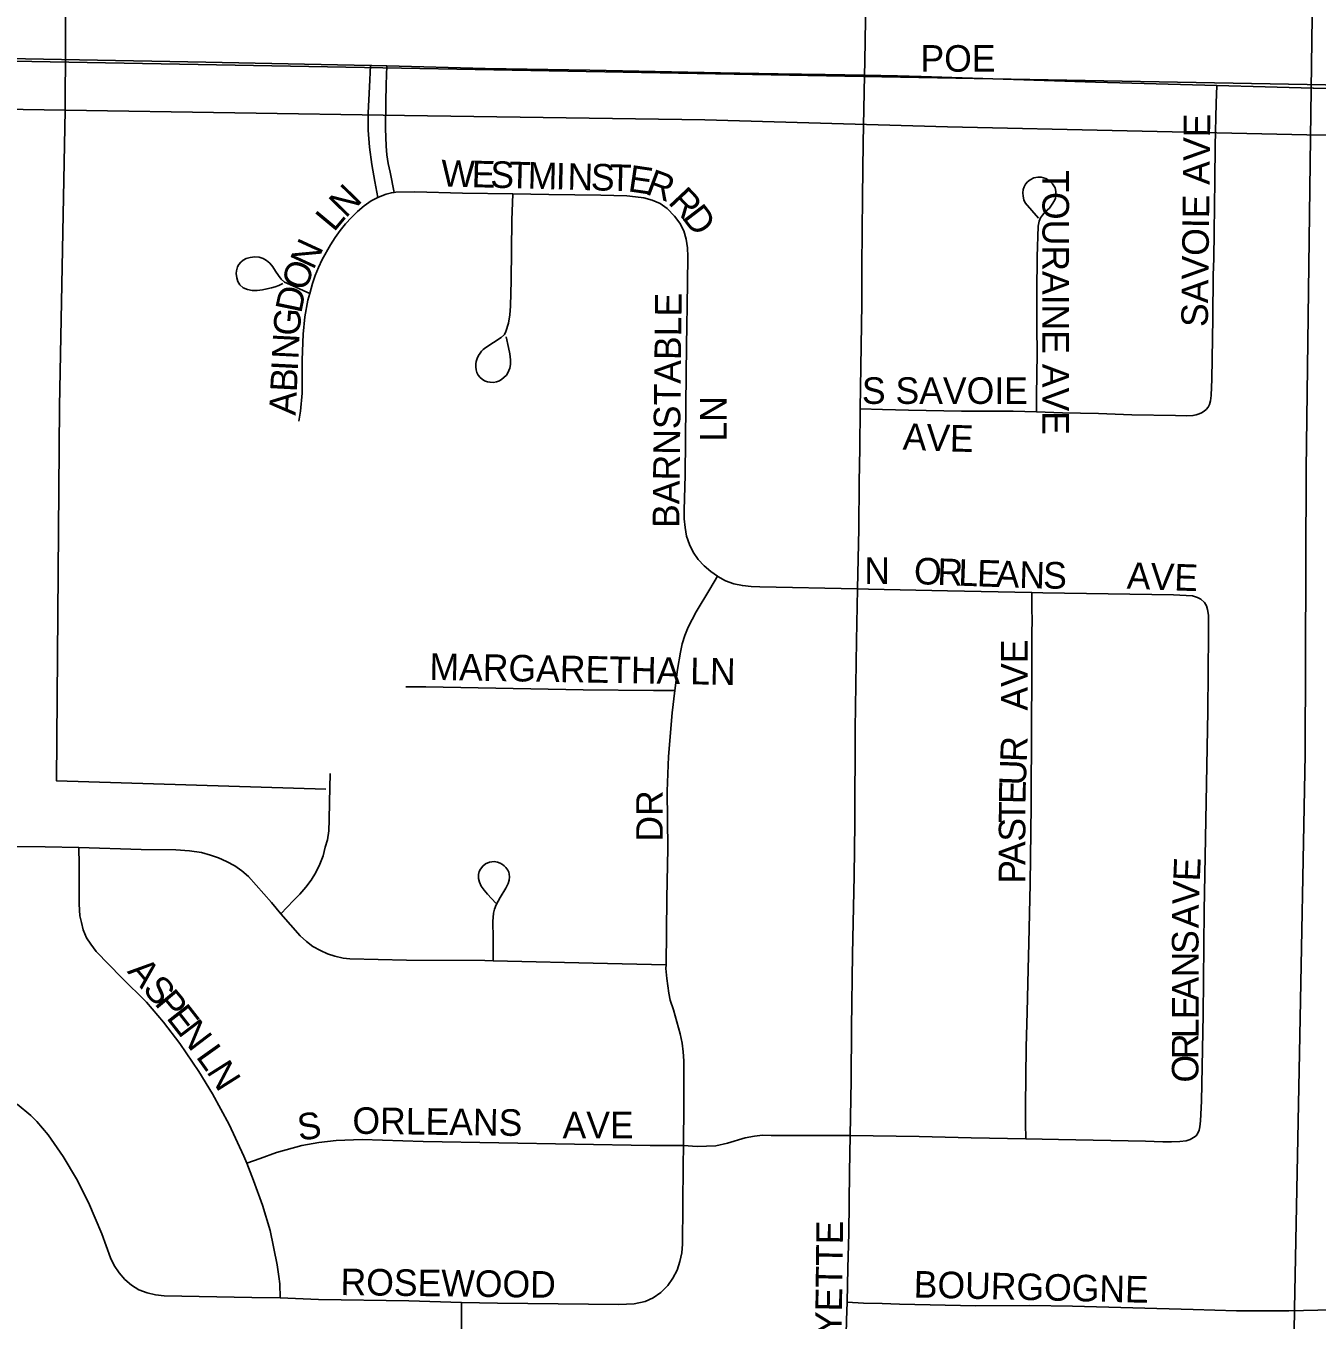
# Model space of a CAD drawing. Extents: x 1443599 to 1910620, y 1028088 to 1361369.
# Drawn here: x 1643273 to 1645702, y 1233402 to 1235837 of the extents above; entities that cross this region are included whole.
import ezdxf

# ---------------------------------------------------------------- set-up
doc = ezdxf.new("R2010")
doc.units = 0
for name, color, linetype in [('GM_X_City_Street', 7, 'Continuous'), ('GM_X_City_Street_Text', 7, 'Continuous'), ('GM_X_Minor_River', 7, 'Continuous'), ('GM_X_Section', 7, 'Continuous')]:
    doc.layers.add(name, color=color, linetype=linetype)

msp = doc.modelspace()

# ---------------------------------------------------------------- linework, layer by layer
at = {"layer": 'GM_X_City_Street'}
for points in [[(1644850.4, 1235743.8), (1644850.8, 1235769.3), (1644852.8, 1235887.3), (1644854.7, 1235951.3)], [(1642046.8, 1235796.5), (1642151.4, 1235793.8), (1642266.3, 1235792), (1642512.4, 1235789), (1642758.5, 1235783.8), (1643135.9, 1235776.9), (1643611.7, 1235768.1), (1643921, 1235761.9)], [(1643934.9, 1235514), (1643929.4, 1235543.9), (1643923.5, 1235575.9), (1643919.3, 1235608.2), (1643917, 1235640.6), (1643916.9, 1235673.2), (1643919.2, 1235721.9), (1643921, 1235761.9)], [(1643921, 1235761.9), (1643923.5, 1235761.8), (1643952, 1235761.1)], [(1643965.8, 1235523.4), (1643958.1, 1235561.2), (1643954.7, 1235577.5), (1643952.3, 1235593.9), (1643950.7, 1235610.4), (1643949.4, 1235643.5), (1643949.9, 1235693.3), (1643950.9, 1235726.4), (1643952, 1235761.1)], [(1643952, 1235761.1), (1644136.7, 1235756.3), (1644333.7, 1235753), (1644579.7, 1235748.2), (1644687.8, 1235746.6), (1644776.7, 1235745.3), (1644850.4, 1235743.8)], [(1644842.4, 1235116.3), (1644845.2, 1235313.9), (1644845.6, 1235384.5), (1644846.8, 1235514.9), (1644847.9, 1235616.7), (1644850.4, 1235743.8)], [(1644850.4, 1235743.8), (1644912.8, 1235742.4), (1644957.1, 1235741.5), (1645285.1, 1235730.7), (1645513, 1235724.4)], [(1645489.1, 1235111.6), (1645492.9, 1235114.7), (1645496.7, 1235119.5), (1645499.6, 1235124.5), (1645501.5, 1235131.5), (1645502.7, 1235141.3), (1645503.8, 1235171.8), (1645505.7, 1235286.7), (1645506.4, 1235367.4), (1645507.4, 1235399.3), (1645508, 1235448.4), (1645509.4, 1235546.1), (1645510.3, 1235611.2), (1645512.2, 1235691.4), (1645513, 1235724.4)], [(1645513, 1235724.4), (1645604.1, 1235721.9), (1645694.6, 1235719.5), (1645695.2, 1235719.4), (1645793.6, 1235717.1), (1645892, 1235714.9)], [(1645173.7, 1235110.4), (1645174, 1235141.3), (1645175, 1235220.5), (1645174.5, 1235270.1), (1645174.4, 1235336.4), (1645175.3, 1235402.2), (1645177, 1235459.9), (1645179.2, 1235469.2), (1645181.7, 1235475.7), (1645185.5, 1235480.7), (1645191.2, 1235487.1), (1645198.2, 1235493.7), (1645203.7, 1235501.1), (1645207.8, 1235508), (1645209.5, 1235512.2), (1645210.6, 1235517.4), (1645210.4, 1235525), (1645208.8, 1235531.9), (1645204.3, 1235539.5), (1645198.2, 1235545.3), (1645191.3, 1235549.5), (1645182.6, 1235551.8), (1645176.3, 1235551.8), (1645169, 1235550.6), (1645161.8, 1235547.1), (1645156.8, 1235542.9), (1645153.5, 1235538.6), (1645150.5, 1235533.6), (1645149.2, 1235528.6), (1645148.5, 1235522.5), (1645149, 1235516), (1645150.3, 1235509.5), (1645152.7, 1235503.9), (1645177.6, 1235475.1)], [(1643806.9, 1235332.9), (1643811.9, 1235352), (1643817.1, 1235367.3), (1643823.2, 1235382.2), (1643830.2, 1235396.8), (1643846.1, 1235425), (1643854.8, 1235438.6), (1643864.3, 1235451.7), (1643874.5, 1235464.2), (1643885.5, 1235476), (1643897, 1235487.5), (1643909.2, 1235498), (1643922.4, 1235507.3), (1643934.9, 1235514)], [(1643934.9, 1235514), (1643936.1, 1235514.6), (1643950.8, 1235520.2)], [(1643950.8, 1235520.2), (1643960.5, 1235522.6), (1643965.8, 1235523.4)], [(1643965.8, 1235523.4), (1643968.9, 1235523.8), (1644004.6, 1235524.1), (1644094.3, 1235521.6), (1644189.1, 1235520.5)], [(1644176.7, 1235251.9), (1644180.9, 1235231.7), (1644183.5, 1235219.7), (1644184.4, 1235208.4), (1644184.4, 1235199.4), (1644183.2, 1235192.9), (1644181.5, 1235188), (1644179.9, 1235184.1), (1644176.9, 1235179.8), (1644172.1, 1235175), (1644168.4, 1235172.2), (1644163.9, 1235169), (1644158.5, 1235167), (1644152.4, 1235165.8), (1644146.3, 1235166.1), (1644141.2, 1235167), (1644135.8, 1235168.8), (1644131.3, 1235171.7), (1644127.5, 1235175.3), (1644123.8, 1235179.4), (1644121.4, 1235184.5), (1644120.3, 1235189.4), (1644119.1, 1235195.3), (1644119.3, 1235200.7), (1644120, 1235205.5), (1644121.8, 1235210.8), (1644124.5, 1235216.5), (1644127.4, 1235221), (1644130.3, 1235224.4), (1644133.5, 1235228), (1644138.4, 1235231.8), (1644167.2, 1235250.1), (1644173.3, 1235256.1), (1644176, 1235261.9), (1644180.8, 1235277.3), (1644183.5, 1235293.2), (1644184.6, 1235309.3), (1644186, 1235357.8), (1644187.2, 1235470.9), (1644189.1, 1235520.5)], [(1644189.1, 1235520.5), (1644256.8, 1235519.6), (1644354.6, 1235518.3), (1644403.4, 1235516.7), (1644419.6, 1235515.2), (1644435.6, 1235512.8), (1644451.1, 1235508.8), (1644465.9, 1235502.3), (1644479.2, 1235492.9), (1644493.2, 1235478.6)], [(1644574, 1234801.3), (1644561.3, 1234810.1), (1644548.7, 1234820.7), (1644537.6, 1234832.8), (1644528.2, 1234846.3), (1644521, 1234861), (1644515.9, 1234876.6), (1644512.9, 1234892.8), (1644511.5, 1234909.2), (1644511.3, 1234925.6), (1644513, 1234991.4), (1644514.5, 1235123), (1644515.9, 1235236.8), (1644516.4, 1235271.2), (1644516.9, 1235311.2), (1644517.4, 1235353.1), (1644517.9, 1235402.5), (1644517.3, 1235419.1), (1644515.2, 1235435.4), (1644510.8, 1235451), (1644503.1, 1235465.5), (1644493.2, 1235478.6)], [(1643756.3, 1235351.9), (1643748.9, 1235348.1), (1643742, 1235345.5), (1643734.9, 1235343.5), (1643726.5, 1235341.7), (1643718, 1235340.1), (1643708.1, 1235338.6), (1643698.9, 1235338.8), (1643689.7, 1235340.4), (1643681.6, 1235343.9), (1643675.5, 1235349.3), (1643671.6, 1235355.7), (1643669.6, 1235362.8), (1643668.8, 1235370.5), (1643669.1, 1235376.1), (1643670.9, 1235383), (1643673.6, 1235387.6), (1643677.7, 1235392.4), (1643681.6, 1235396), (1643687.4, 1235399), (1643695, 1235401.1), (1643703.5, 1235402.4), (1643711.8, 1235401.3), (1643719.5, 1235399.3), (1643725.4, 1235395.5), (1643732, 1235389.9), (1643737.4, 1235383), (1643742.8, 1235375.1), (1643748, 1235366.8), (1643753.2, 1235359.8), (1643759.5, 1235354.4), (1643774.9, 1235347.4), (1643806.9, 1235332.9)], [(1643786.4, 1235093.2), (1643789.7, 1235111.7), (1643793, 1235145.8), (1643792.7, 1235176), (1643792.7, 1235208.4), (1643794.5, 1235256.8), (1643797.8, 1235289), (1643803.7, 1235320.8), (1643806.9, 1235332.9)], [(1644837.4, 1234777.6), (1644839.8, 1234890.7), (1644840.3, 1234978.5), (1644841.4, 1235042.1), (1644842.4, 1235116.3)], [(1644842.4, 1235116.3), (1644884.6, 1235115.2), (1644933, 1235114), (1645033.1, 1235111.6), (1645129.9, 1235111.7), (1645173.7, 1235110.4)], [(1645173.7, 1235110.4), (1645222.8, 1235108.9), (1645290.3, 1235107.2), (1645353.3, 1235105.2), (1645435.5, 1235103.8), (1645456.7, 1235102.9), (1645468.1, 1235103.6), (1645474.4, 1235104.8), (1645480.1, 1235106.5), (1645484.4, 1235108.4), (1645489.1, 1235111.6)], [(1644493.7, 1234586.2), (1644498.5, 1234625.9), (1644504.1, 1234658.3), (1644507.8, 1234674.3), (1644512.5, 1234690), (1644518.5, 1234705.3), (1644534, 1234734.3), (1644559.3, 1234776.7), (1644574, 1234801.3)], [(1644837.4, 1234777.6), (1644653.5, 1234781.5), (1644637, 1234782.1), (1644620.7, 1234783.7), (1644604.6, 1234787.1), (1644589.3, 1234792.9), (1644574.9, 1234800.7), (1644574, 1234801.3)], [(1644823.7, 1233749.2), (1644825.6, 1233852.8), (1644826.1, 1233952.4), (1644827.7, 1234090.1), (1644830.8, 1234237.6), (1644832.2, 1234336.8), (1644833.2, 1234514.1), (1644835.4, 1234680.1), (1644837.4, 1234777.6)], [(1644837.4, 1234777.6), (1644858, 1234777.2), (1645006.6, 1234774), (1645165, 1234770.8)], [(1645153.7, 1233742.9), (1645153.4, 1233771.6), (1645153.1, 1233804.5), (1645154.7, 1233915.6), (1645156.7, 1233981.3), (1645158.6, 1234062), (1645159.5, 1234111.1), (1645162, 1234222.9), (1645163.9, 1234370.3), (1645164.1, 1234386.7), (1645164.9, 1234625.9), (1645165.1, 1234641.6), (1645165.3, 1234657.7), (1645165.5, 1234690.4), (1645165.7, 1234722.3), (1645165.5, 1234736.2), (1645165, 1234770.8)], [(1645165, 1234770.8), (1645185.6, 1234770.3), (1645431.4, 1234766.1), (1645467.1, 1234764.4), (1645476.5, 1234761.6), (1645483.2, 1234758.3)], [(1645474.2, 1233748.7), (1645477.6, 1233754), (1645480, 1233759.2), (1645481.2, 1233765.7), (1645482.7, 1233776.6), (1645484.4, 1233813.6), (1645487.6, 1233976.4), (1645489.6, 1234171.8), (1645496.5, 1234547.4), (1645497.5, 1234693), (1645497.3, 1234728), (1645495.9, 1234738.9), (1645494, 1234745.5), (1645489.8, 1234752.1), (1645483.2, 1234758.3)], [(1643987.5, 1234593.5), (1644025.4, 1234593.2), (1644321.6, 1234587.7), (1644453.3, 1234586.6), (1644493.7, 1234586.2)], [(1644477.1, 1234070.6), (1644478.6, 1234195.4), (1644480.6, 1234290), (1644479.1, 1234396.8), (1644481.8, 1234462), (1644488.6, 1234544.3), (1644493.7, 1234586.2)], [(1643752.6, 1234166.2), (1643776.7, 1234191.2), (1643788.4, 1234203.3), (1643799.4, 1234216.2), (1643809.4, 1234229.9), (1643818.3, 1234244.3), (1643825.8, 1234259.4), (1643832, 1234275.2), (1643836.3, 1234291.4), (1643840.5, 1234305.5), (1643842.8, 1234322.5), (1643843.4, 1234342.8), (1643843.9, 1234376.6), (1643845.6, 1234430.2)], [(1643072.3, 1234178.3), (1643073.4, 1234194.9), (1643075, 1234209.3), (1643078.3, 1234224.2), (1643080.8, 1234231.1), (1643084.1, 1234238.7), (1643088.4, 1234245.9), (1643092.7, 1234252.4), (1643098.5, 1234259.3), (1643104.3, 1234265.3), (1643110.4, 1234270.1), (1643115.3, 1234274), (1643121.9, 1234278.3), (1643128.6, 1234282.3), (1643137, 1234286.3), (1643144.4, 1234289.2), (1643153, 1234291.1), (1643161.8, 1234291.9), (1643194.4, 1234293.5), (1643309.4, 1234292.1), (1643372.8, 1234290.9)], [(1643688.4, 1233697.3), (1643683.3, 1233710.4), (1643655.2, 1233769.8), (1643624.2, 1233827.5), (1643598.7, 1233869.5), (1643562.4, 1233922.2), (1643532, 1233962.7), (1643500.1, 1234000.1), (1643452.7, 1234046.4), (1643405.1, 1234095.4), (1643395, 1234109), (1643387.2, 1234121.4), (1643381, 1234136.2), (1643377.5, 1234149.9), (1643374.7, 1234162.7), (1643373.2, 1234184.5), (1643373.5, 1234258.8), (1643372.8, 1234290.9)], [(1643372.8, 1234290.9), (1643489.8, 1234287.5), (1643555, 1234286.4), (1643581, 1234284.7), (1643603.1, 1234281.4), (1643620.1, 1234276.7), (1643635.6, 1234271.4), (1643650.6, 1234264.6), (1643665.8, 1234256.5), (1643679.5, 1234246.9), (1643692.1, 1234236.3), (1643735.2, 1234187.4), (1643752.6, 1234166.2)], [(1644152.3, 1234078.1), (1644151.7, 1234120.2), (1644151.3, 1234151.8), (1644152.7, 1234167.7), (1644154.3, 1234175.1), (1644157.5, 1234183.1), (1644165.1, 1234197), (1644175.6, 1234214.5), (1644180.3, 1234223.5), (1644182.1, 1234229.9), (1644182.6, 1234236.1), (1644182.4, 1234240.7), (1644181.5, 1234244.8), (1644179.8, 1234248.5), (1644176, 1234253.5), (1644172.7, 1234256.7), (1644169.4, 1234259.2), (1644165.4, 1234261.7), (1644160, 1234263.5), (1644153.7, 1234264.5), (1644145.1, 1234263.6), (1644137.8, 1234260.4), (1644132.3, 1234256), (1644128.1, 1234250.3), (1644125.9, 1234245.6), (1644124.5, 1234240.1), (1644124.3, 1234232.6), (1644126.1, 1234226), (1644129.4, 1234218.4), (1644134.8, 1234210.5), (1644141.5, 1234203.4), (1644157.3, 1234186.1)], [(1643752.6, 1234166.2), (1643788.9, 1234124.7), (1643800.6, 1234114.2), (1643812.6, 1234104.8), (1643827.4, 1234097.2), (1643840.3, 1234091.3), (1643854, 1234086.7), (1643869.9, 1234083.1), (1643882.2, 1234081.7), (1643989.1, 1234079.3), (1644136.2, 1234078.4), (1644152.3, 1234078.1)], [(1644152.3, 1234078.1), (1644367, 1234072.7), (1644477.1, 1234070.6)], [(1644509.8, 1233730.3), (1644510.9, 1233807.8), (1644510.6, 1233889.8), (1644509.5, 1233906.5), (1644507.3, 1233923.1), (1644504, 1233940.4), (1644491, 1233985.4), (1644485.1, 1234004.1), (1644482.4, 1234016.9), (1644478.9, 1234044.5), (1644477, 1234063.6), (1644477.1, 1234070.6)], [(1643256.9, 1233808.4), (1643282.1, 1233787.2), (1643293.8, 1233775.6), (1643315, 1233750.5), (1643343.3, 1233710.1), (1643368.6, 1233667.6), (1643390.8, 1233623.5), (1643415.9, 1233564.3), (1643432, 1233519.3), (1643439.1, 1233504.5), (1643448.3, 1233490.9), (1643459.2, 1233478.5), (1643471.7, 1233467.8), (1643485.7, 1233459.3), (1643501, 1233453.1), (1643517, 1233449.5), (1643533.4, 1233447.9), (1643697.9, 1233444.8), (1643751.4, 1233443.8)], [(1643688.4, 1233697.3), (1643713.7, 1233706.3), (1643744.6, 1233717.2), (1643792.1, 1233730.2), (1643824.2, 1233736.4), (1643856.8, 1233739.9), (1643905.9, 1233741.5), (1644020.2, 1233738.2), (1644447.1, 1233730.2), (1644509.8, 1233730.3)], [(1644509.8, 1233730.3), (1644535.5, 1233728.6), (1644570.6, 1233730), (1644593, 1233735), (1644625.8, 1233745), (1644643.6, 1233748.3), (1644658.3, 1233749.7), (1644674.7, 1233749.5), (1644805.8, 1233749.5), (1644823.7, 1233749.2)], [(1644817.6, 1233435.6), (1644819.4, 1233500), (1644820.7, 1233565.6), (1644822.5, 1233680.3), (1644823.7, 1233749.2)], [(1644823.7, 1233749.2), (1644953.2, 1233747.4), (1645051.4, 1233744.9), (1645153.7, 1233742.9)], [(1645153.7, 1233742.9), (1645215.3, 1233741.7), (1645379.1, 1233738.4), (1645411.5, 1233737.7), (1645427.6, 1233737.7), (1645443.7, 1233738.3), (1645455.2, 1233739.3), (1645463, 1233741.6), (1645469.1, 1233745.3), (1645474.2, 1233748.7)], [(1644092.4, 1233435.3), (1644160.4, 1233434.2), (1644388.6, 1233431.1), (1644417.2, 1233432.7), (1644438.2, 1233437.1), (1644452.8, 1233444.1), (1644467.3, 1233453.8), (1644480.8, 1233467.3), (1644490, 1233480.8), (1644498.1, 1233495.9), (1644503.1, 1233512.4), (1644506.6, 1233528.4), (1644508, 1233544.8), (1644509.2, 1233692.6), (1644509.8, 1233730.3)], [(1643751.4, 1233443.8), (1643750.6, 1233470.5), (1643748.8, 1233484), (1643745.9, 1233505.9), (1643732.3, 1233570.9), (1643718.2, 1233618.4), (1643701.4, 1233664.6), (1643688.4, 1233697.3)], [(1643751.4, 1233443.8), (1643823.2, 1233441.1), (1643993.7, 1233438.4), (1644092.4, 1233435.3)], [(1644087.7, 1233102.4), (1644088.5, 1233144.6), (1644090.5, 1233259.6), (1644092.6, 1233374.3), (1644092.4, 1233407.1), (1644092.4, 1233435.3)], [(1644812.2, 1233088.8), (1644812.6, 1233123.6), (1644814.9, 1233320.2), (1644816.6, 1233401.8), (1644817.6, 1233435.6)], [(1644817.6, 1233435.6), (1644848.8, 1233434), (1644883.5, 1233433.2), (1644916, 1233432.3), (1645060.1, 1233428.9), (1645160.7, 1233429.7), (1645241.8, 1233428.3), (1645468.6, 1233422.1), (1645550.4, 1233419.6), (1645648.7, 1233419.7), (1645730.7, 1233421.1), (1645878, 1233425.8), (1645973.1, 1233427.9)]]:
    msp.add_lwpolyline(points, dxfattribs=at)
at = {"layer": 'GM_X_Minor_River'}
for points in [[(1643837.2, 1234400.7), (1643330.7, 1234416.3), (1643336.1, 1235120.6), (1643346.7, 1235678.3), (1643350.9, 1236428.8), (1643352.4, 1237032.9), (1641989.1, 1237074.8)], [(1645695.9, 1236081.5), (1645689.3, 1235626), (1645681.4, 1235002), (1645679.2, 1234466.2)], [(1647799, 1235333.5), (1647649.7, 1235595.1), (1647133.2, 1235610.9), (1646668.6, 1235615.6), (1646258, 1235621.3), (1645841.6, 1235631.2), (1645682.3, 1235631.9), (1645006.6, 1235646.9), (1644550.2, 1235659.6), (1643985.5, 1235668.2), (1643346.7, 1235678.3), (1642755.9, 1235687.5), (1642393.5, 1235690.4)], [(1645679.2, 1234466.2), (1645668.6, 1233904.4), (1645659.4, 1233423), (1645651.5, 1232903.3), (1645640.5, 1232638.6), (1645115.8, 1232646.5), (1645101.4, 1232203.2), (1645103.9, 1231910.2)]]:
    msp.add_lwpolyline(points, dxfattribs=at)
at = {"layer": 'GM_X_Section'}
for points in [[(1642126.5, 1241101.1), (1647460.7, 1240949), (1647351.7, 1235696.1), (1642066.7, 1235791.6)], [(1642066.7, 1235791.6), (1647351.7, 1235696.1), (1647258, 1230369.4), (1644385, 1230387), (1641921.5, 1230497.2)]]:
    msp.add_lwpolyline(points, close=True, dxfattribs=at)

# ---------------------------------------------------------------- texts
at = {"layer": 'GM_X_City_Street_Text'}
for s, rotation, p in [('POE', 0, (1644955.7, 1235750.3)), ('SAVOIE AVE', 89.319, (1645496.2, 1235270)), ('W', 358.5036, (1644053.8, 1235534.7)), ('E', 358.4969, (1644111, 1235533.2)), ('S', 358.4969, (1644146.2, 1235532.3)), ('T', 358.4969, (1644181.3, 1235531.4)), ('M', 358.5024, (1644216.5, 1235530.5)), ('I', 358.5133, (1644269.3, 1235529.1)), ('N', 358.492, (1644291.3, 1235528.5)), ('S', 358.4969, (1644335.3, 1235527.4)), ('T', 358.4969, (1644370.5, 1235526.4)), ('E', 351.7462, (1644404.1, 1235525.6)), ('R', 339.5605, (1644436.2, 1235521.3)), ('TOURAINE AVE', 270, (1645185.1, 1235564.9)), ('N', 45.6955, (1643874.4, 1235473.6)), ('R', 313.179, (1644479.4, 1235503.7)), ('D', 307.3727, (1644505.7, 1235475.9)), ('L', 50.2049, (1643852.5, 1235447.4)), ('N', 65.2142, (1643813.9, 1235376)), ('O', 69.9889, (1643799.3, 1235335.7)), ('D', 78.3342, (1643790.9, 1235294.4)), ('BARNSTABLE', 89.3701, (1644501.8, 1234892)), ('G', 85.6901, (1643787.8, 1235252.3)), ('N', 87.0881, (1643785.6, 1235208.6)), ('I', 87.0669, (1643784.5, 1235186.6)), ('B', 87.0697, (1643782.5, 1235147.1)), ('S SAVOIE', 0, (1644845.6, 1235125.5)), ('A', 87.0917, (1643780.2, 1235103.2)), ('LN', 90, (1644591.3, 1235054.5)), ('A', 357.7041, (1644921.8, 1235039.5)), ('V', 357.8085, (1644965.9, 1235037.8)), ('E', 358.4612, (1645010.4, 1235036.1)), ('N', 0, (1644850, 1234786.7)), ('O', 357.9234, (1644942.8, 1234786.7)), ('R', 357.9384, (1644986.8, 1234785.1)), ('L', 357.9234, (1645026.3, 1234783.7)), ('E', 357.9581, (1645061.5, 1234782.4)), ('A', 357.9234, (1645096.7, 1234781.1)), ('N', 358.2363, (1645141, 1234779.5)), ('S', 359.6058, (1645186.3, 1234778.2)), ('AVE', 357.9557, (1645343.2, 1234777.9)), ('AVE', 90, (1645157.4, 1234548.5)), ('MARGARETHA LN', 359.0368, (1644031.9, 1234606.3)), ('R', 87.7899, (1645155.5, 1234451.2)), ('U', 87.8797, (1645153.9, 1234407.2)), ('DR', 90, (1644471.1, 1234302.1)), ('E', 88.716, (1645153.1, 1234372.2)), ('T', 89.8907, (1645153.1, 1234337.3)), ('S', 90, (1645153.1, 1234302.1)), ('A', 89.9812, (1645153, 1234258.1)), ('P', 89.9727, (1645153, 1234222.9)), ('E', 87.5128, (1645481.1, 1234226.7)), ('V', 87.7041, (1645479.3, 1234182.8)), ('A', 89.1694, (1645478.7, 1234139.1)), ('S', 89.9727, (1645478.7, 1234090.9)), ('N', 89.9928, (1645478.7, 1234046.9)), ('A', 310.3429, (1643462.4, 1234057.4)), ('S', 310.3198, (1643490.9, 1234023.9)), ('A', 89.9928, (1645478.7, 1234002.9)), ('P', 309.8336, (1643513.6, 1233997.1)), ('E', 89.9727, (1645478.7, 1233967.7)), ('E', 308.0283, (1643535.9, 1233970.4)), ('N', 307.2328, (1643557.5, 1233942.8)), ('L', 89.9956, (1645478.7, 1233932.5)), ('R', 89.9757, (1645478.6, 1233892.9)), ('L', 305.4329, (1643591.8, 1233897.6)), ('N', 302.2046, (1643611.8, 1233869.6)), ('O', 90, (1645478.6, 1233848.9)), ('S', 7.4105, (1643787, 1233739.6)), ('ORLEANS', 359.2244, (1643887, 1233752.7)), ('AVE', 0, (1644282.5, 1233743.9)), ('LAFAYETTE', 89.2855, (1644805.4, 1233206.3)), ('ROSEWOOD', 359.2806, (1643864.7, 1233449.1)), ('BOURGOGNE', 358.6844, (1644942.6, 1233444.7))]:
    msp.add_text(s, height=50, rotation=rotation, dxfattribs=at).set_placement(p)

doc.saveas('drawing.dxf')
